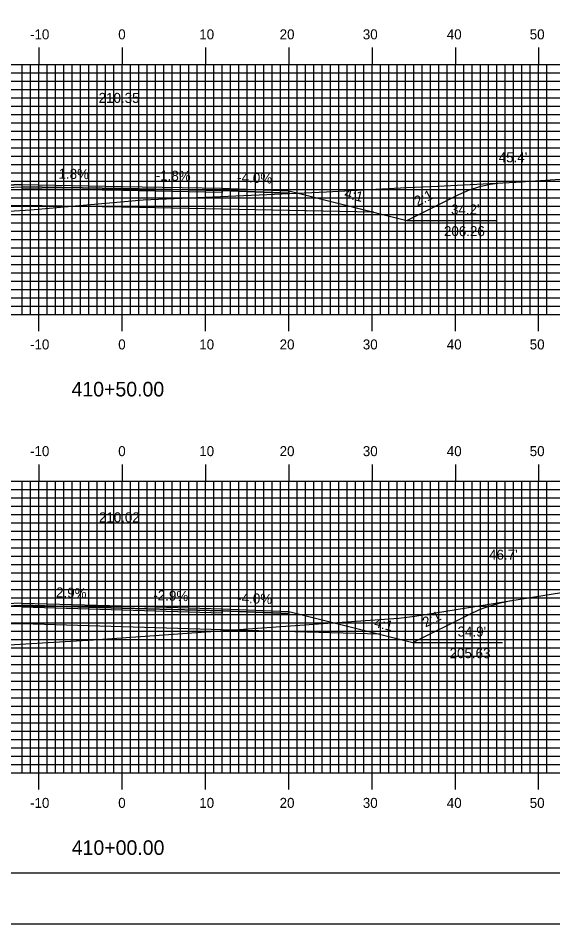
# Model space of a CAD drawing. Extents: x 853316 to 853659, y 364785 to 365005.
# Drawn here: x 853469.3 to 853533.5, y 364785.1 to 364893.8 of the extents above; entities that cross this region are included whole.
import ezdxf

# ---------------------------------------------------------------- set-up
doc = ezdxf.new("R2010")
doc.units = 0
for name, color, linetype in [('ANNOTATION', 7, 'Continuous'), ('BORDER', 7, 'Continuous'), ('D_Roadway_Centerline', 7, 'Continuous'), ('D_Roadway_Centerline_Text', 7, 'Continuous'), ('D_Roadway_Edge_Shoulder', 7, 'Continuous'), ('D_Roadway_Edge_TW', 7, 'Continuous'), ('D_Roadway_Pavement', 7, 'Continuous'), ('D_Roadway_SlopeLines', 7, 'Continuous'), ('D_Roadway_SubGrade', 7, 'Continuous'), ('D_Text_Standard', 7, 'Continuous'), ('H_V ANNOTATION', 7, 'Continuous'), ('MAJOR', 7, 'Continuous'), ('MINOR', 7, 'Continuous'), ('PDRAIN', 7, 'Continuous'), ('PLOT BOUNDARY', 7, 'Continuous'), ('S_Roadway_Centerline', 7, 'Continuous')]:
    doc.layers.add(name, color=color, linetype=linetype)

msp = doc.modelspace()

# ---------------------------------------------------------------- linework, layer by layer
at = {"layer": 'BORDER'}
msp.add_lwpolyline([(853332.16, 364791.23), (853652.16, 364791.23), (853652.16, 365001.23), (853332.16, 365001.23)], close=True, dxfattribs=at)
at = {"layer": 'D_Roadway_Centerline'}
msp.add_lwpolyline([(853447.85, 364870), (853451.58, 364870.94), (853461.76, 364873.48), (853469.76, 364873.8), (853481.76, 364873.58), (853493.76, 364873.36), (853501.76, 364873.04), (853511.93, 364870.49), (853515.93, 364869.49), (853522.19, 364872.62), (853523.44, 364873.18), (853524.69, 364873.59), (853525.94, 364873.87), (853527.19, 364874)], dxfattribs=at)
at = {"layer": 'D_Roadway_Edge_Shoulder'}
for points in [[(853469.76, 364873.8), (853461.76, 364873.48), (853461.76, 364873.23), (853469.76, 364873.55)], [(853493.76, 364873.36), (853501.76, 364873.04), (853501.76, 364872.79), (853493.76, 364873.11)], [(853469.76, 364823.6), (853461.76, 364823.28), (853461.76, 364823.03), (853469.76, 364823.35)], [(853493.76, 364822.91), (853501.76, 364822.59), (853501.76, 364822.34), (853493.76, 364822.66)]]:
    msp.add_lwpolyline(points, close=True, dxfattribs=at)
at = {"layer": 'D_Roadway_Edge_TW'}
for points in [[(853469.76, 364873.55), (853469.76, 364873.8), (853481.76, 364873.58), (853493.76, 364873.36), (853493.76, 364873.11), (853481.76, 364873.33)], [(853469.76, 364823.35), (853469.76, 364823.6), (853481.76, 364823.26), (853493.76, 364822.91), (853493.76, 364822.66), (853481.76, 364823.01)]]:
    msp.add_lwpolyline(points, close=True, dxfattribs=at)
at = {"layer": 'D_Roadway_Pavement'}
for points in [[(853469.76, 364873.3), (853469.76, 364873.55), (853481.76, 364873.33), (853493.76, 364873.11), (853493.76, 364872.86), (853481.76, 364873.08)], [(853469.76, 364823.1), (853469.76, 364823.35), (853481.76, 364823.01), (853493.76, 364822.66), (853493.76, 364822.41), (853481.76, 364822.76)]]:
    msp.add_lwpolyline(points, close=True, dxfattribs=at)
at = {"layer": 'D_Roadway_SlopeLines'}
for points in [[(853515.93, 364869.49), (853522.19, 364872.62), (853523.44, 364873.18), (853524.69, 364873.59), (853525.94, 364873.87), (853527.19, 364874)], [(853501.76, 364873.04), (853515.93, 364869.49)], [(853516.66, 364818.86), (853523.42, 364822.25), (853524.67, 364822.82), (853525.92, 364823.28), (853527.17, 364823.64), (853528.42, 364823.9)], [(853501.76, 364822.59), (853516.66, 364818.86)]]:
    msp.add_lwpolyline(points, dxfattribs=at)
at = {"layer": 'D_Roadway_SubGrade'}
for points in [[(853469.76, 364871.3), (853451.58, 364870.94), (853461.76, 364873.48), (853461.76, 364873.23), (853469.76, 364873.55), (853481.76, 364873.33), (853493.76, 364873.11), (853501.76, 364872.79), (853501.76, 364873.04), (853511.93, 364870.49), (853493.76, 364870.86), (853481.76, 364871.08)], [(853469.76, 364821.1), (853451.58, 364820.74), (853461.76, 364823.28), (853461.76, 364823.03), (853469.76, 364823.35), (853481.76, 364823.01), (853493.76, 364822.66), (853501.76, 364822.34), (853501.76, 364822.59), (853512.66, 364819.86), (853493.76, 364820.41), (853481.76, 364820.76)]]:
    msp.add_lwpolyline(points, close=True, dxfattribs=at)
at = {"layer": 'MAJOR'}
for p, q in [((853471.76, 364890.24), (853471.76, 364888.23)), ((853481.76, 364890.24), (853481.76, 364888.23)), ((853491.76, 364890.24), (853491.76, 364888.23)), ((853501.76, 364890.24), (853501.76, 364888.23)), ((853511.76, 364890.24), (853511.76, 364888.23)), ((853521.76, 364890.24), (853521.76, 364888.23)), ((853531.76, 364890.24), (853531.76, 364888.23)), ((853341.76, 364888.23), (853621.76, 364888.23)), ((853341.76, 364888.23), (853621.76, 364888.23)), ((853471.76, 364858.23), (853471.76, 364888.23)), ((853481.76, 364858.23), (853481.76, 364888.23)), ((853491.76, 364858.23), (853491.76, 364888.23)), ((853501.76, 364858.23), (853501.76, 364888.23)), ((853511.76, 364858.23), (853511.76, 364888.23)), ((853521.76, 364858.23), (853521.76, 364888.23)), ((853531.76, 364858.23), (853531.76, 364888.23)), ((853341.76, 364883.23), (853621.76, 364883.23)), ((853341.76, 364878.23), (853621.76, 364878.23)), ((853341.76, 364873.23), (853621.76, 364873.23)), ((853341.76, 364868.23), (853621.76, 364868.23)), ((853341.76, 364863.23), (853621.76, 364863.23)), ((853341.76, 364858.23), (853621.76, 364858.23)), ((853341.76, 364858.23), (853621.76, 364858.23)), ((853471.76, 364856.23), (853471.76, 364858.23)), ((853481.76, 364856.23), (853481.76, 364858.23)), ((853491.76, 364856.23), (853491.76, 364858.23)), ((853501.76, 364856.23), (853501.76, 364858.23)), ((853511.76, 364856.23), (853511.76, 364858.23)), ((853521.76, 364856.23), (853521.76, 364858.23)), ((853531.76, 364856.23), (853531.76, 364858.23)), ((853471.76, 364840.24), (853471.76, 364838.23)), ((853481.76, 364840.24), (853481.76, 364838.23)), ((853491.76, 364840.24), (853491.76, 364838.23)), ((853501.76, 364840.24), (853501.76, 364838.23)), ((853511.76, 364840.24), (853511.76, 364838.23)), ((853521.76, 364840.24), (853521.76, 364838.23)), ((853531.76, 364840.24), (853531.76, 364838.23)), ((853341.76, 364838.23), (853621.76, 364838.23)), ((853341.76, 364838.23), (853621.76, 364838.23)), ((853471.76, 364803.23), (853471.76, 364838.23)), ((853481.76, 364803.23), (853481.76, 364838.23)), ((853491.76, 364803.23), (853491.76, 364838.23)), ((853501.76, 364803.23), (853501.76, 364838.23)), ((853511.76, 364803.23), (853511.76, 364838.23)), ((853521.76, 364803.23), (853521.76, 364838.23)), ((853531.76, 364803.23), (853531.76, 364838.23)), ((853341.76, 364833.23), (853621.76, 364833.23)), ((853341.76, 364828.23), (853621.76, 364828.23)), ((853341.76, 364823.23), (853621.76, 364823.23)), ((853341.76, 364818.23), (853621.76, 364818.23)), ((853341.76, 364813.23), (853621.76, 364813.23)), ((853341.76, 364808.23), (853621.76, 364808.23)), ((853341.76, 364803.23), (853621.76, 364803.23)), ((853341.76, 364803.23), (853621.76, 364803.23)), ((853471.76, 364801.23), (853471.76, 364803.23)), ((853481.76, 364801.23), (853481.76, 364803.23)), ((853491.76, 364801.23), (853491.76, 364803.23)), ((853501.76, 364801.23), (853501.76, 364803.23)), ((853511.76, 364801.23), (853511.76, 364803.23)), ((853521.76, 364801.23), (853521.76, 364803.23)), ((853531.76, 364801.23), (853531.76, 364803.23))]:
    msp.add_line(p, q, dxfattribs=at)
at = {"layer": 'MINOR'}
for p, q in [((853469.76, 364858.23), (853469.76, 364888.23)), ((853470.76, 364858.23), (853470.76, 364888.23)), ((853472.76, 364858.23), (853472.76, 364888.23)), ((853473.76, 364858.23), (853473.76, 364888.23)), ((853474.76, 364858.23), (853474.76, 364888.23)), ((853475.76, 364858.23), (853475.76, 364888.23)), ((853476.76, 364858.23), (853476.76, 364888.23)), ((853477.76, 364858.23), (853477.76, 364888.23)), ((853478.76, 364858.23), (853478.76, 364888.23)), ((853479.76, 364858.23), (853479.76, 364888.23)), ((853480.76, 364858.23), (853480.76, 364888.23)), ((853482.76, 364858.23), (853482.76, 364888.23)), ((853483.76, 364858.23), (853483.76, 364888.23)), ((853484.76, 364858.23), (853484.76, 364888.23)), ((853485.76, 364858.23), (853485.76, 364888.23)), ((853486.76, 364858.23), (853486.76, 364888.23)), ((853487.76, 364858.23), (853487.76, 364888.23)), ((853488.76, 364858.23), (853488.76, 364888.23)), ((853489.76, 364858.23), (853489.76, 364888.23)), ((853490.76, 364858.23), (853490.76, 364888.23)), ((853492.76, 364858.23), (853492.76, 364888.23)), ((853493.76, 364858.23), (853493.76, 364888.23)), ((853494.76, 364858.23), (853494.76, 364888.23)), ((853495.76, 364858.23), (853495.76, 364888.23)), ((853496.76, 364858.23), (853496.76, 364888.23)), ((853497.76, 364858.23), (853497.76, 364888.23)), ((853498.76, 364858.23), (853498.76, 364888.23)), ((853499.76, 364858.23), (853499.76, 364888.23)), ((853500.76, 364858.23), (853500.76, 364888.23)), ((853502.76, 364858.23), (853502.76, 364888.23)), ((853503.76, 364858.23), (853503.76, 364888.23)), ((853504.76, 364858.23), (853504.76, 364888.23)), ((853505.76, 364858.23), (853505.76, 364888.23)), ((853506.76, 364858.23), (853506.76, 364888.23)), ((853507.76, 364858.23), (853507.76, 364888.23)), ((853508.76, 364858.23), (853508.76, 364888.23)), ((853509.76, 364858.23), (853509.76, 364888.23)), ((853510.76, 364858.23), (853510.76, 364888.23)), ((853512.76, 364858.23), (853512.76, 364888.23)), ((853513.76, 364858.23), (853513.76, 364888.23)), ((853514.76, 364858.23), (853514.76, 364888.23)), ((853515.76, 364858.23), (853515.76, 364888.23)), ((853516.76, 364858.23), (853516.76, 364888.23)), ((853517.76, 364858.23), (853517.76, 364888.23)), ((853518.76, 364858.23), (853518.76, 364888.23)), ((853519.76, 364858.23), (853519.76, 364888.23)), ((853520.76, 364858.23), (853520.76, 364888.23)), ((853522.76, 364858.23), (853522.76, 364888.23)), ((853523.76, 364858.23), (853523.76, 364888.23)), ((853524.76, 364858.23), (853524.76, 364888.23)), ((853525.76, 364858.23), (853525.76, 364888.23)), ((853526.76, 364858.23), (853526.76, 364888.23)), ((853527.76, 364858.23), (853527.76, 364888.23)), ((853528.76, 364858.23), (853528.76, 364888.23)), ((853529.76, 364858.23), (853529.76, 364888.23)), ((853530.76, 364858.23), (853530.76, 364888.23)), ((853532.76, 364858.23), (853532.76, 364888.23)), ((853341.76, 364887.23), (853621.76, 364887.23)), ((853341.76, 364886.23), (853621.76, 364886.23)), ((853341.76, 364885.23), (853621.76, 364885.23)), ((853341.76, 364884.23), (853621.76, 364884.23)), ((853341.76, 364882.23), (853621.76, 364882.23)), ((853341.76, 364881.23), (853621.76, 364881.23)), ((853341.76, 364880.23), (853621.76, 364880.23)), ((853341.76, 364879.23), (853621.76, 364879.23)), ((853341.76, 364877.23), (853621.76, 364877.23)), ((853341.76, 364876.23), (853621.76, 364876.23)), ((853341.76, 364875.23), (853621.76, 364875.23)), ((853341.76, 364874.23), (853621.76, 364874.23)), ((853341.76, 364872.23), (853621.76, 364872.23)), ((853341.76, 364871.23), (853621.76, 364871.23)), ((853341.76, 364870.23), (853621.76, 364870.23)), ((853341.76, 364869.23), (853621.76, 364869.23)), ((853341.76, 364867.23), (853621.76, 364867.23)), ((853341.76, 364866.23), (853621.76, 364866.23)), ((853341.76, 364865.23), (853621.76, 364865.23)), ((853341.76, 364864.23), (853621.76, 364864.23)), ((853341.76, 364862.23), (853621.76, 364862.23)), ((853341.76, 364861.23), (853621.76, 364861.23)), ((853341.76, 364860.23), (853621.76, 364860.23)), ((853341.76, 364859.23), (853621.76, 364859.23)), ((853469.76, 364803.23), (853469.76, 364838.23)), ((853470.76, 364803.23), (853470.76, 364838.23)), ((853472.76, 364803.23), (853472.76, 364838.23)), ((853473.76, 364803.23), (853473.76, 364838.23)), ((853474.76, 364803.23), (853474.76, 364838.23)), ((853475.76, 364803.23), (853475.76, 364838.23)), ((853476.76, 364803.23), (853476.76, 364838.23)), ((853477.76, 364803.23), (853477.76, 364838.23)), ((853478.76, 364803.23), (853478.76, 364838.23)), ((853479.76, 364803.23), (853479.76, 364838.23)), ((853480.76, 364803.23), (853480.76, 364838.23)), ((853482.76, 364803.23), (853482.76, 364838.23)), ((853483.76, 364803.23), (853483.76, 364838.23)), ((853484.76, 364803.23), (853484.76, 364838.23)), ((853485.76, 364803.23), (853485.76, 364838.23)), ((853486.76, 364803.23), (853486.76, 364838.23)), ((853487.76, 364803.23), (853487.76, 364838.23)), ((853488.76, 364803.23), (853488.76, 364838.23)), ((853489.76, 364803.23), (853489.76, 364838.23)), ((853490.76, 364803.23), (853490.76, 364838.23)), ((853492.76, 364803.23), (853492.76, 364838.23)), ((853493.76, 364803.23), (853493.76, 364838.23)), ((853494.76, 364803.23), (853494.76, 364838.23)), ((853495.76, 364803.23), (853495.76, 364838.23)), ((853496.76, 364803.23), (853496.76, 364838.23)), ((853497.76, 364803.23), (853497.76, 364838.23)), ((853498.76, 364803.23), (853498.76, 364838.23)), ((853499.76, 364803.23), (853499.76, 364838.23)), ((853500.76, 364803.23), (853500.76, 364838.23)), ((853502.76, 364803.23), (853502.76, 364838.23)), ((853503.76, 364803.23), (853503.76, 364838.23)), ((853504.76, 364803.23), (853504.76, 364838.23)), ((853505.76, 364803.23), (853505.76, 364838.23)), ((853506.76, 364803.23), (853506.76, 364838.23)), ((853507.76, 364803.23), (853507.76, 364838.23)), ((853508.76, 364803.23), (853508.76, 364838.23)), ((853509.76, 364803.23), (853509.76, 364838.23)), ((853510.76, 364803.23), (853510.76, 364838.23)), ((853512.76, 364803.23), (853512.76, 364838.23)), ((853513.76, 364803.23), (853513.76, 364838.23)), ((853514.76, 364803.23), (853514.76, 364838.23)), ((853515.76, 364803.23), (853515.76, 364838.23)), ((853516.76, 364803.23), (853516.76, 364838.23)), ((853517.76, 364803.23), (853517.76, 364838.23)), ((853518.76, 364803.23), (853518.76, 364838.23)), ((853519.76, 364803.23), (853519.76, 364838.23)), ((853520.76, 364803.23), (853520.76, 364838.23)), ((853522.76, 364803.23), (853522.76, 364838.23)), ((853523.76, 364803.23), (853523.76, 364838.23)), ((853524.76, 364803.23), (853524.76, 364838.23)), ((853525.76, 364803.23), (853525.76, 364838.23)), ((853526.76, 364803.23), (853526.76, 364838.23)), ((853527.76, 364803.23), (853527.76, 364838.23)), ((853528.76, 364803.23), (853528.76, 364838.23)), ((853529.76, 364803.23), (853529.76, 364838.23)), ((853530.76, 364803.23), (853530.76, 364838.23)), ((853532.76, 364803.23), (853532.76, 364838.23)), ((853341.76, 364837.23), (853621.76, 364837.23)), ((853341.76, 364836.23), (853621.76, 364836.23)), ((853341.76, 364835.23), (853621.76, 364835.23)), ((853341.76, 364834.23), (853621.76, 364834.23)), ((853341.76, 364832.23), (853621.76, 364832.23)), ((853341.76, 364831.23), (853621.76, 364831.23)), ((853341.76, 364830.23), (853621.76, 364830.23)), ((853341.76, 364829.23), (853621.76, 364829.23)), ((853341.76, 364827.23), (853621.76, 364827.23)), ((853341.76, 364826.23), (853621.76, 364826.23)), ((853341.76, 364825.23), (853621.76, 364825.23)), ((853341.76, 364824.23), (853621.76, 364824.23)), ((853341.76, 364822.23), (853621.76, 364822.23)), ((853341.76, 364821.23), (853621.76, 364821.23)), ((853341.76, 364820.23), (853621.76, 364820.23)), ((853341.76, 364819.23), (853621.76, 364819.23)), ((853341.76, 364817.23), (853621.76, 364817.23)), ((853341.76, 364816.23), (853621.76, 364816.23)), ((853341.76, 364815.23), (853621.76, 364815.23)), ((853341.76, 364814.23), (853621.76, 364814.23)), ((853341.76, 364812.23), (853621.76, 364812.23)), ((853341.76, 364811.23), (853621.76, 364811.23)), ((853341.76, 364810.23), (853621.76, 364810.23)), ((853341.76, 364809.23), (853621.76, 364809.23)), ((853341.76, 364807.23), (853621.76, 364807.23)), ((853341.76, 364806.23), (853621.76, 364806.23)), ((853341.76, 364805.23), (853621.76, 364805.23)), ((853341.76, 364804.23), (853621.76, 364804.23))]:
    msp.add_line(p, q, dxfattribs=at)
at = {"layer": 'PDRAIN'}
for p, q in [((853515.93, 364869.49), (853526.7, 364869.49)), ((853516.66, 364818.86), (853527.43, 364818.86))]:
    msp.add_line(p, q, dxfattribs=at)
at = {"layer": 'PLOT BOUNDARY'}
msp.add_lwpolyline([(853315.97, 364785.11), (853655.97, 364785.11), (853655.97, 365005.11), (853315.97, 365005.11)], close=True, dxfattribs=at)
at = {"layer": 'S_Roadway_Centerline'}
for points in [[(853341.76, 364865.84), (853356.16, 364866.46), (853366.14, 364866.68), (853382.04, 364867.48), (853382.97, 364867.53), (853404.92, 364868.62), (853417.92, 364869.21), (853430.2, 364869.26), (853438.03, 364869.75), (853465.49, 364870.45), (853470.73, 364870.78), (853484.26, 364871.97), (853500.06, 364872.67), (853501.84, 364872.73), (853506.29, 364872.95), (853515.89, 364873.45), (853518.86, 364873.58), (853529.02, 364874.09), (853536.1, 364874.57)], [(853341.76, 364812.92), (853344.5, 364813.14), (853347.01, 364813.28), (853350.12, 364813.44), (853369.35, 364813.65), (853379.97, 364814.25), (853427.05, 364815.97), (853430, 364816.11), (853430.31, 364816.12), (853437.12, 364816.56), (853456.88, 364817.9), (853464.71, 364818.39), (853478.31, 364819.19), (853505.33, 364821.12), (853514.36, 364821.74), (853514.96, 364821.79), (853516.88, 364822.05), (853540.71, 364825.86)]]:
    msp.add_lwpolyline(points, dxfattribs=at)

# ---------------------------------------------------------------- texts
at = {"layer": 'ANNOTATION'}
for s, rotation, p in [('1.8%', 358.9424, (853474.1, 364874.52)), ('-1.8%', 358.9424, (853485.78, 364874.31)), ('-4.0%', 357.7094, (853495.55, 364874.09)), ('4:1', 345.9638, (853508.35, 364872.25)), ('2:1', 26.5651, (853517.2, 364871.17)), ('2.9%', 358.3477, (853473.8, 364824.29)), ('-2.9%', 358.3477, (853485.48, 364823.95)), ('-4.0%', 357.7094, (853495.55, 364823.64)), ('2:1', 26.5651, (853518.19, 364820.66)), ('4:1', 345.9638, (853511.93, 364820.76))]:
    msp.add_text(s, height=1.2, rotation=rotation, dxfattribs=at).set_placement(p)
for s, p in [("34.2'", (853521.24, 364870.22)), ('206.26', (853520.39, 364867.62)), ("34.9'", (853522.03, 364819.59)), ('205.63', (853521.07, 364816.99))]:
    msp.add_text(s, height=1.2, dxfattribs=at).set_placement(p)
at = {"layer": 'D_Roadway_Centerline'}
for s, p in [('C', (853481.75, 364873.58)), ('L', (853481.76, 364873.57)), ('C', (853481.75, 364823.26)), ('L', (853481.76, 364823.25))]:
    msp.add_text(s, height=0.0146, dxfattribs=at).set_placement(p)
at = {"layer": 'D_Roadway_Centerline_Text'}
for s, p in [('210.35', (853478.93, 364883.61)), ('210.02', (853478.96, 364833.29))]:
    msp.add_text(s, height=1.2, dxfattribs=at).set_placement(p)
at = {"layer": 'D_Text_Standard'}
for s, p in [("45.4'", (853526.97, 364876.48)), ("46.7'", (853525.81, 364828.81))]:
    msp.add_text(s, height=1.2, dxfattribs=at).set_placement(p)
at = {"layer": 'H_V ANNOTATION'}
for s, height, p in [('-10', 1.2, (853470.69, 364891.23)), ('0', 1.2, (853481.28, 364891.23)), ('10', 1.2, (853491.01, 364891.23)), ('20', 1.2, (853500.66, 364891.23)), ('30', 1.2, (853510.65, 364891.23)), ('40', 1.2, (853520.73, 364891.23)), ('50', 1.2, (853530.69, 364891.23)), ('-10', 1.2, (853470.69, 364854.03)), ('0', 1.2, (853481.28, 364854.03)), ('10', 1.2, (853491.01, 364854.03)), ('20', 1.2, (853500.66, 364854.03)), ('30', 1.2, (853510.65, 364854.03)), ('40', 1.2, (853520.73, 364854.03)), ('50', 1.2, (853530.69, 364854.03)), ('410+50.00', 1.75, (853475.67, 364848.39)), ('-10', 1.2, (853470.69, 364841.23)), ('0', 1.2, (853481.28, 364841.23)), ('10', 1.2, (853491.01, 364841.23)), ('20', 1.2, (853500.66, 364841.23)), ('30', 1.2, (853510.65, 364841.23)), ('40', 1.2, (853520.73, 364841.23)), ('50', 1.2, (853530.69, 364841.23)), ('-10', 1.2, (853470.69, 364799.03)), ('0', 1.2, (853481.28, 364799.03)), ('10', 1.2, (853491.01, 364799.03)), ('20', 1.2, (853500.66, 364799.03)), ('30', 1.2, (853510.65, 364799.03)), ('40', 1.2, (853520.73, 364799.03)), ('50', 1.2, (853530.69, 364799.03)), ('410+00.00', 1.75, (853475.7, 364793.39))]:
    msp.add_text(s, height=height, dxfattribs=at).set_placement(p)

doc.saveas('drawing.dxf')
